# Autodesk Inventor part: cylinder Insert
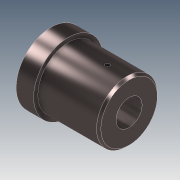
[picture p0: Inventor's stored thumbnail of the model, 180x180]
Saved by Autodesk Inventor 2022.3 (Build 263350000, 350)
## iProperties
Created: 2023-08
Part Number: cylinder Insert
Material: Steel, Alloy
Document SubType Name: Modeling
Designer: irinventor.com
Mass: 138.972 g
Surface Area: 58.9102 cm^2
Volume: 17.9783 cm^3
Density: 7.73 g/cm^3
Appearance: Semi-Polished(3)
Author: irinventor.com
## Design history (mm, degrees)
sketch "Sketch1"
  geometry: L1 (0, 0)-(42, 0); L2 (45, 6)-(9, 6); L3 (9, 6)-(9, 16); L4 (9, 16)-(17, 16); L5 (17, 16)-(17, 14); L6 (17, 14)-(45, 14); L7 (45, 14)-(45, 6); 1 further point
  constraints: 14 end point, 4 horizontal, 3 vertical, 1 midpoint
  dimensions: "d0" = 12 diameter of L2 L1; "d1" = 32 diameter of L4 L1; "d2" = 8 distance of L3.end L4.end; "d3" = 28 distance of L5.end L6.end; "d11" = 2 distance from line of L6 point (13, 16); "d28" = 28 diameter of L6 L1 (derived)
revolve "Revolution1" sketch "Sketch1" stored, may be unused: angle "d4" = 90 deg
chamfer "Chamfer1" distance "d5" = 1; stored, may be unused: second distance "d6" = 2, angle "d7" = 45 deg
chamfer "Chamfer2" distance "d8" = 1; stored, may be unused: second distance "d9" = 2, angle "d10" = 45 deg
sketch "Sketch2"
  geometry: 2 further points
  constraints: 1 vertical alignment
  dimensions: "d19" = 11 distance of point (0, 11) point (0, 0)
hole "Hole1" sketch "Sketch2" at (0, 11) diameter "d12" = 3; stored, may be unused: countersink angle "d16" = 90 deg, drill point angle "d18" = 118 deg; dims "d13" = 5, "d14" = 4, "d15" = 2, "d17" = 25
workplane "Work Plane1"
sketch "Sketch3"
  geometry: L1 (22, 16)-(22, -16) reference; 2 further points
  constraints: 1 horizontal alignment
  dimensions: "d27" = 26 distance from line of L1 point (-4, 0)
hole "Hole2" sketch "Sketch3" at (-4, 0) diameter "d20" = 2.013; stored, may be unused: countersink angle "d24" = 90 deg, drill point angle "d26" = 118 deg; dims "d21" = 5, "d22" = 4, "d23" = 2, "d25" = 6
body "Solid1"
